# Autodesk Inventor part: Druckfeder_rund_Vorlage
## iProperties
Author: swi
Created: 2002-05
Part Number: Druckfeder_rund_Vorlage
Material: Stahl (schweißbar)
Document SubType Name: Modellieren
Designer: swi
Description: Druckfeder
Control State: 0
Master: False
Checked Out: False
Last Check In Date: 2002-06-07
PropertySet Name: Design Tracking Control
Last Check In By: swi
Shininess: 25.0
PropertySet Name: _Private Model Information
Density: 7.86
Volumn: 1.45241812378508
Area: 29.71615046332203
PropertySet Name: Model Information
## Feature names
1. Spirale1
2. Spirale2
3. Spirale3
4. Trennen1
5. Trennen2
